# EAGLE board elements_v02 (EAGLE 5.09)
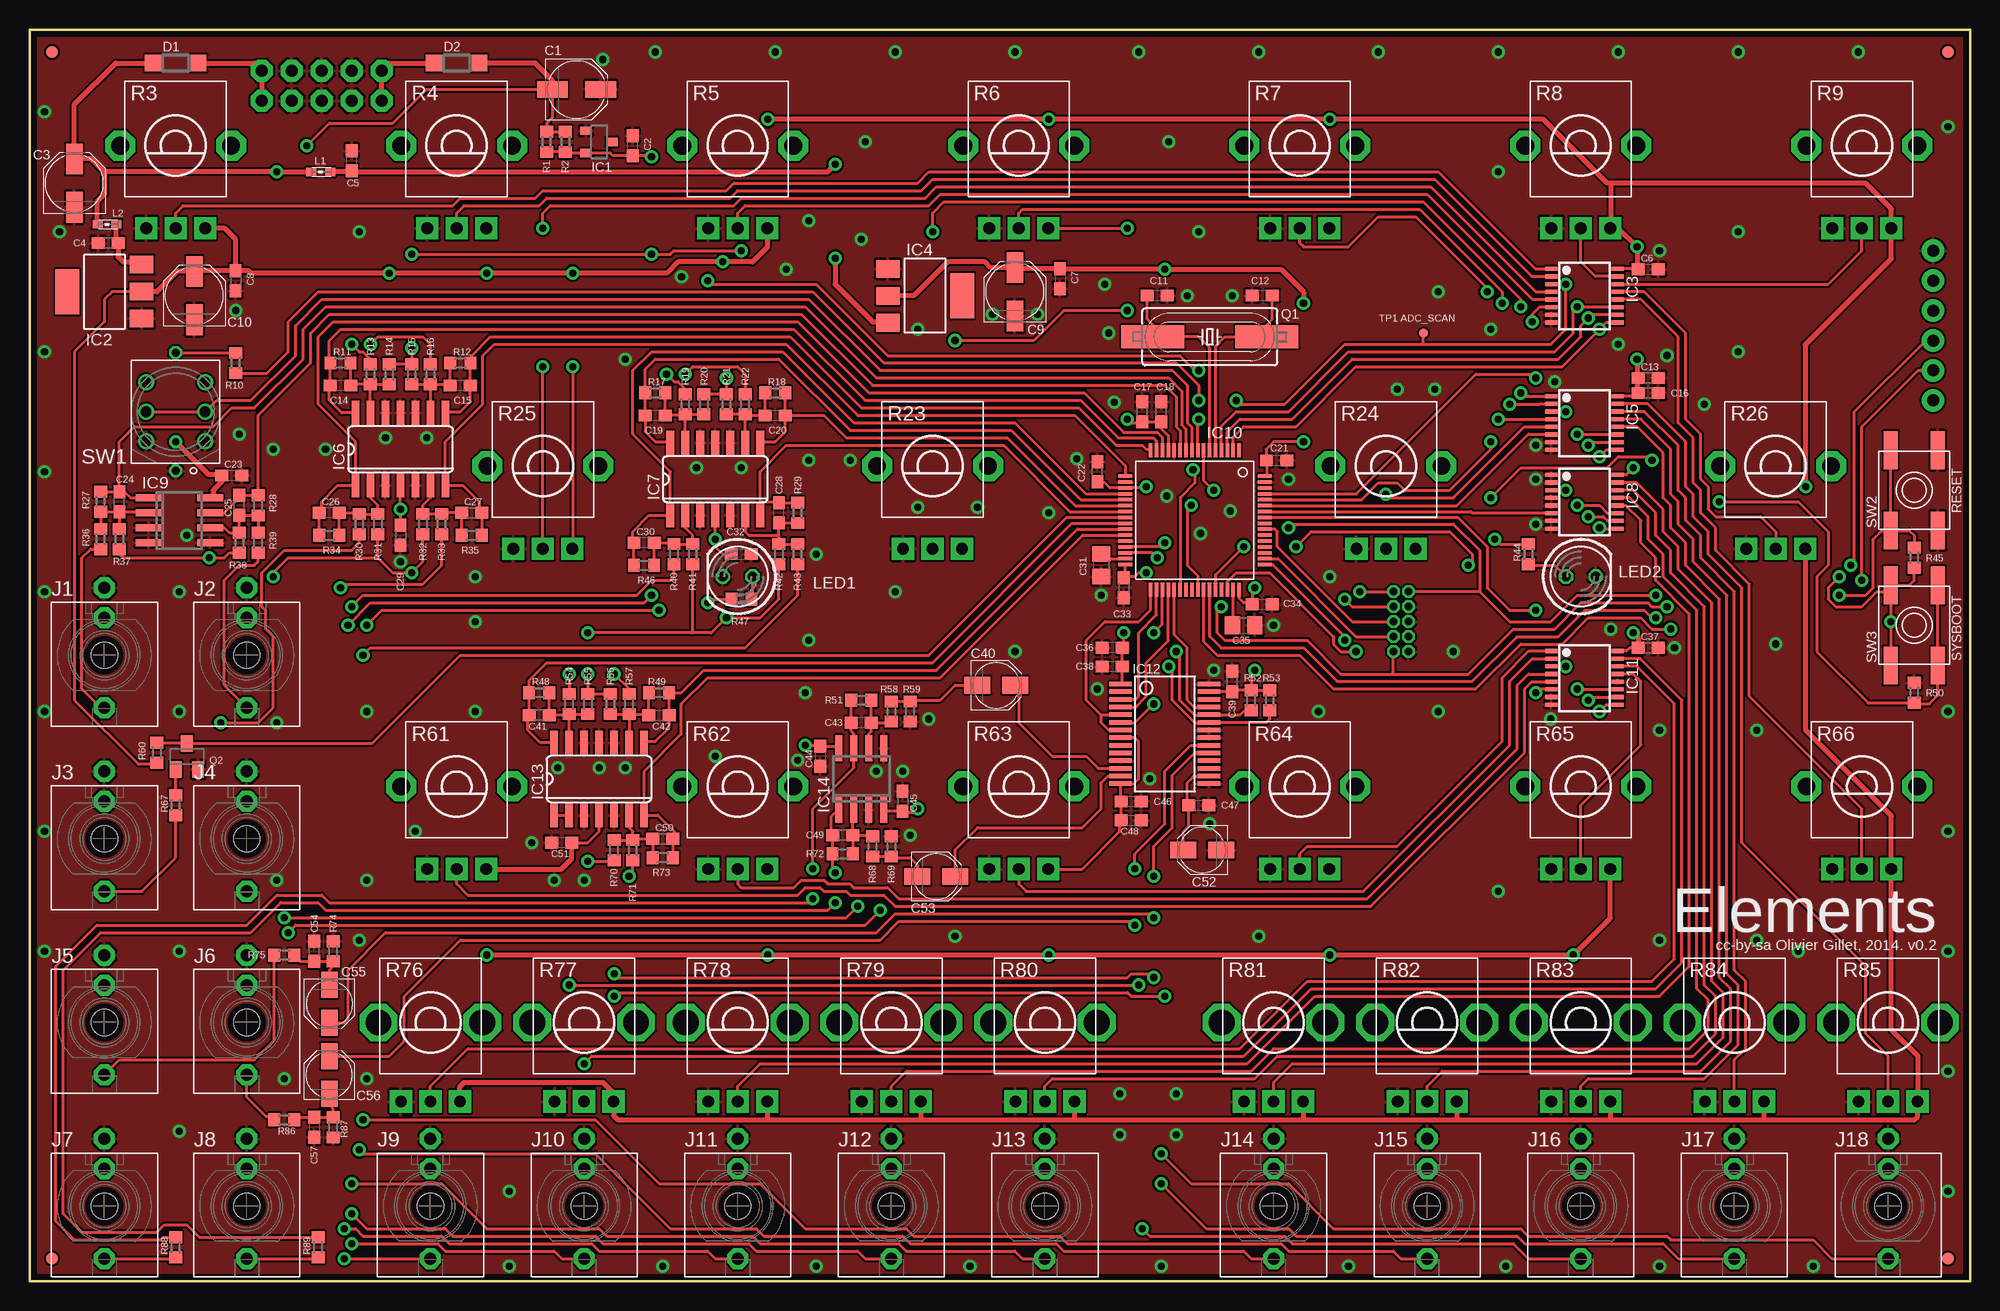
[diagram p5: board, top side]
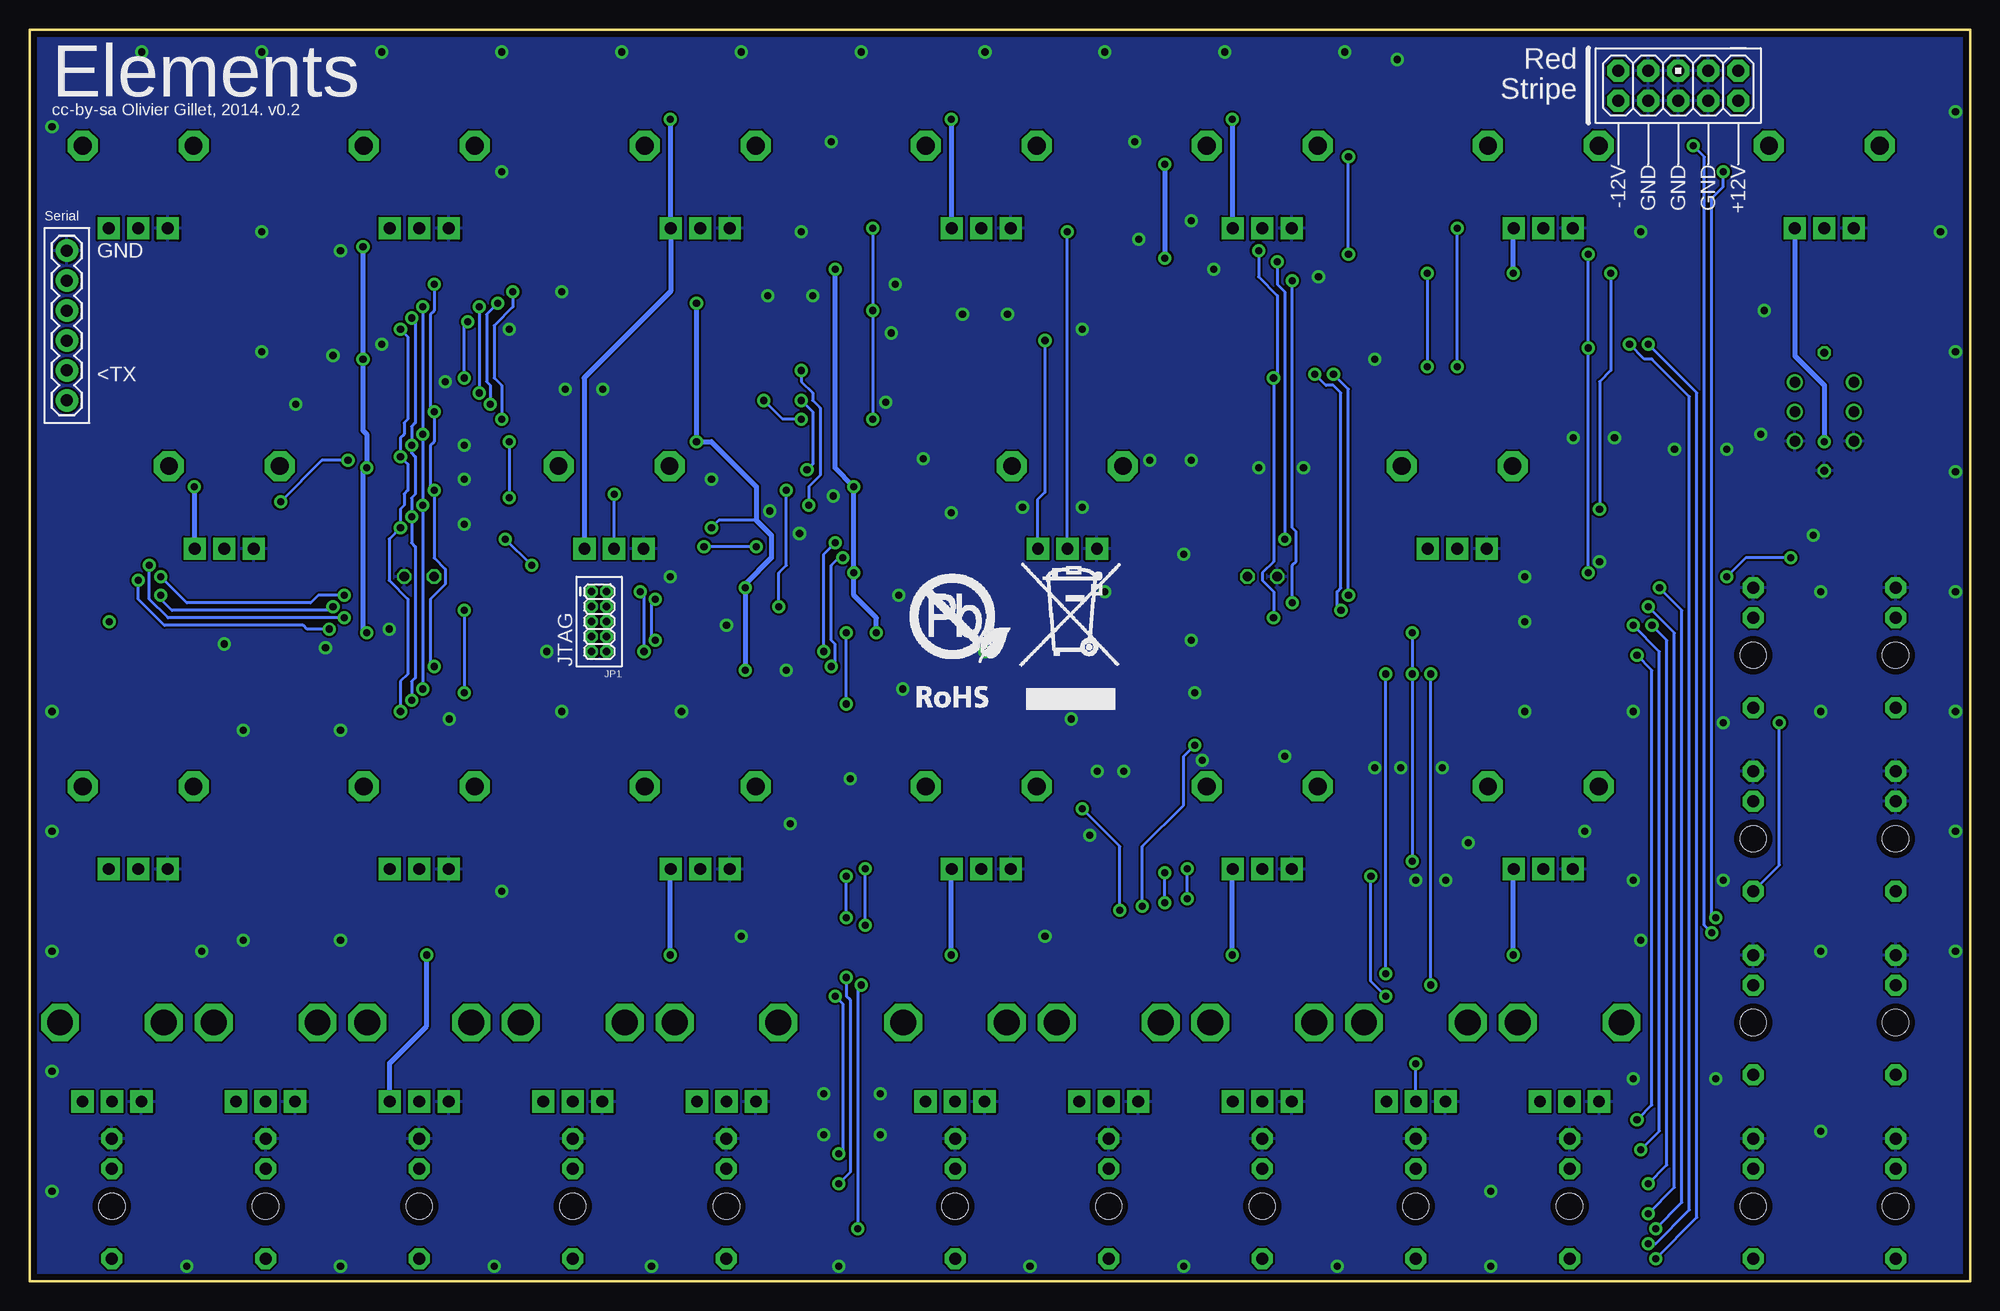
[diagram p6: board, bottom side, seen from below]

Size 164.47 x 106.05 mm. Coordinates in mm from the lower left corner, seen from the top.
Outline: 0,0 164.47,0 164.47,106.05 0,106.05 0,0
Copper layers (1*16): Top 0.035mm / dielectric 1.5mm / Bottom 0.035mm
Design rules "PCBCart-Standard-Fine": minimum track width 8mil, minimum drill 0.4mm, track to track 7mil, track to pad 7mil, pad to pad 7mil, via to via 7mil, smd to smd 7mil, copper to edge 20mil, drill to drill 8mil, minimum pad ring 8mil, minimum via ring 10mil, stop-mask expansion 3mil, vias tented up to drill 25mil, thermal gap 8mil

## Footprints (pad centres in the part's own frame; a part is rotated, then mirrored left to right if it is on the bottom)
PANASONIC_C = smd 2.6 x 1.4: + 2.05,0; - -2.05,0
C0603 = smd 1.1 x 1: 1 -0.85,0; 2 0.85,0
C0805 = smd 1.3 x 1.5: 1 -0.95,0; 2 0.95,0
PANASONIC_B = smd 2.2 x 1.4: + 1.6,0; - -1.6,0
SOD123 = smd 1.4 x 1.4: A 1.9,0; C -1.9,0
FIDUCIAL-1X2 = smd 1 x 1: 1 0,0
DBZ_R-PDSO-G3 = smd 0.7 x 1: 1 -0.95,-1.1; 2 0.95,-1.1; 3 0,1.1
SOT223 = smd 1.499 x 2.007: 1 -2.261,-3.15; 2 0.025,-3.15; 3 2.311,-3.15 | smd 3.81 x 2.007: 4 0,3.15
TSSOP16 = smd 0.35 x 1: 1 -1.95,-2.825; 2 -1.3,-2.825; 3 -0.65,-2.825; 4 0,-2.825; 5 0.65,-2.825; 6 1.3,-2.825; 7 1.95,-2.825; 8 2.6,-2.825; 9 2.6,2.825; 10 1.95,2.825; 11 1.3,2.825; 12 0.65,2.825; 13 0,2.825; 14 -0.65,2.825; 15 -1.3,2.825; 16 -1.95,2.825
SO14 = smd 0.66 x 2.032: 1 -3.81,-3.073; 2 -2.54,-3.073; 3 -1.27,-3.073; 4 0,-3.073; 5 1.27,-3.073; 6 2.54,-3.073; 7 3.81,-3.073; 8 3.81,3.073; 9 2.54,3.073; 10 1.27,3.073; 11 0,3.073; 12 -1.27,3.073; 13 -2.54,3.073; 14 -3.81,3.073
SO08 = smd 0.6 x 2.2: 1 -1.905,-2.6; 2 -0.635,-2.6; 3 0.635,-2.6; 4 1.905,-2.6; 5 1.905,2.6; 6 0.635,2.6; 7 -0.635,2.6; 8 -1.905,2.6
TQFP-10X10-64 = smd 1.2 x 0.3: 1 -5.936,3.75; 2 -5.936,3.25; 3 -5.936,2.75; 4 -5.936,2.25; 5 -5.936,1.75; 6 -5.936,1.25; 7 -5.936,0.75; 8 -5.936,0.25; 9 -5.936,-0.25; 10 -5.936,-0.75; 11 -5.936,-1.25; 12 -5.936,-1.75; 13 -5.936,-2.25; 14 -5.936,-2.75; 15 -5.936,-3.25; 16 -5.936,-3.75; 33 5.886,-3.75; 34 5.886,-3.25; 35 5.886,-2.75; 36 5.886,-2.25; 37 5.886,-1.75; 38 5.886,-1.25; 39 5.886,-0.75; 40 5.886,-0.25; 41 5.886,0.25; 42 5.886,0.75; 43 5.886,1.25; 44 5.886,1.75; 45 5.886,2.25; 46 5.886,2.75; 47 5.886,3.25; 48 5.886,3.75 | smd 0.3 x 1.2: 17 -3.75,-5.911; 18 -3.25,-5.911; 19 -2.75,-5.911; 20 -2.25,-5.911; 21 -1.75,-5.911; 22 -1.25,-5.911; 23 -0.75,-5.911; 24 -0.25,-5.911; 25 0.25,-5.911; 26 0.75,-5.911; 27 1.25,-5.911; 28 1.75,-5.911; 29 2.25,-5.911; 30 2.75,-5.911; 31 3.25,-5.911; 32 3.75,-5.911; 49 3.75,5.936; 50 3.25,5.936; 51 2.75,5.936; 52 2.25,5.936; 53 1.75,5.936; 54 1.25,5.936; 55 0.75,5.936; 56 0.25,5.936; 57 -0.25,5.936; 58 -0.75,5.936; 59 -1.25,5.936; 60 -1.75,5.936; 61 -2.25,5.936; 62 -2.75,5.936; 63 -3.25,5.936; 64 -3.75,5.936
SSOP28 = smd 0.381 x 1.905: 1 -4.55,-3.752; 2 -3.9,-3.752; 3 -3.25,-3.752; 4 -2.6,-3.752; 5 -1.95,-3.752; 6 -1.3,-3.752; 7 -0.65,-3.752; 8 0,-3.752; 9 0.65,-3.752; 10 1.3,-3.752; 11 1.95,-3.752; 12 2.6,-3.752; 13 3.25,-3.752; 14 3.9,-3.752; 15 3.9,3.752; 16 3.25,3.752; 17 2.6,3.752; 18 1.95,3.752; 19 1.3,3.752; 20 0.65,3.752; 21 0,3.752; 22 -0.65,3.752; 23 -1.3,3.752; 24 -1.95,3.752; 25 -2.6,3.752; 26 -3.25,3.752; 27 -3.9,3.752; 28 -4.55,3.752
WQP_PJ_301M6 = drill 1.016 pad 1.778 octagon: P1 0,-5.715; P2 0,-3.175; P3 0,4.445 | hole 2.2: 0,0
2X5-1.27 = drill 0.61 pad 1.067 octagon: 1 -1.27,3.81; 2 0,3.81; 3 -1.27,2.54; 4 0,2.54; 5 -1.27,1.27; 6 0,1.27; 7 -1.27,0; 8 0,0; 9 -1.27,-1.27; 10 0,-1.27
1X06 = drill 1.016 pad 1.88 round: 1 0,0; 2 2.54,0; 3 5.08,0; 4 7.62,0; 5 10.16,0; 6 12.7,0
AVR_ICSP = drill 1.016 pad 1.88 octagon: 1 -1.27,5.08; 2 1.27,5.08; 3 -1.27,2.54; 4 1.27,2.54; 5 -1.27,0; 6 1.27,0; 7 -1.27,-2.54; 8 1.27,-2.54; 9 -1.27,-5.08; 10 1.27,-5.08
0603 = smd 0.85 x 0.7: 1 -0.9,0; 2 0.7,0
LED5MM = drill 0.813 octagon: A -1.27,0; K 1.27,0
HC49UP = smd 5.334 x 1.93: 1 -4.826,0; 2 4.826,0
SOT23-BEC = smd 1 x 1.4: B -0.95,-1.1; C 0,1.1; E 0.95,-1.1
R0603 = smd 1 x 1.1: 1 -0.85,0; 2 0.85,0
ALPS_POT_VERTICAL_PS = drill 1 pad 1.88 square: P$1 -2.5,7; P$2 0,7; P$3 2.5,7 | drill 1.5 pad 2.54 octagon: P$4 -4.7,0; P$5 4.7,0
ALPS_POT_VERTICAL = drill 1 pad 1.88 square: P$1 -2.5,6.7; P$2 0,6.7; P$3 2.5,6.7 | drill 2.2 pad 3.175 octagon: P$4 -4.4,0; P$5 4.4,0
LP4OA1PBCT = drill 0.7 octagon: L1 5,0; L2 -5,0 | drill 0.9 round: P1 2.5,2.5; P2 0,2.5; P3 -2.5,2.5; P4 2.5,-2.5; P5 0,-2.5; P6 -2.5,-2.5
EVQ-Q2 = smd 3.2 x 1.2: A -3.4,-2; A' 3.4,-2; B -3.4,2; B' 3.4,2
PAD.03X.03 = smd 0.762 x 0.762: P$1 0,0

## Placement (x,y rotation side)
C1  22u  [PANASONIC_C]  46.35,100.97 0 top
C2  100n  [C0603]  51.12,96.2 90 top
C3  22u  [PANASONIC_C]  3.81,93.03 90 top
C4  100n  [C0603]  6.67,87.95 180 top
C5  100n  [C0603]  27.3,94.93 90 top
C6  100n  [C0603]  137.16,85.72 0 top
C7  100n  [C0603]  87.31,84.93 270 top
C8  100n  [C0603]  17.46,84.77 270 top
C9  22u  [PANASONIC_C]  83.5,83.82 90 top
C10  22u  [PANASONIC_C]  13.97,83.5 90 top
C11  18p  [C0603]  95.57,83.5 180 top
C12  18p  [C0603]  104.46,83.5 0 top
C13  100n  [C0603]  137.16,76.52 0 top
C14  3.3n  [C0603]  26.35,75.88 180 top
C15  3.3n  [C0603]  36.51,75.88 0 top
C16  100n  [C0603]  137.16,75.25 0 top
C17  1u  [C0603]  94.3,73.66 90 top
C18  100n  [C0603]  95.89,73.66 90 top
C19  3.3n  [C0603]  53.02,73.34 180 top
C20  3.3n  [C0603]  63.18,73.34 0 top
C21  100n  [C0603]  105.66,69.53 0 top
C22  100n  [C0603]  90.49,68.58 90 top
C23  100n  [C0603]  17.14,68.26 0 top
C24  3.3n  [C0603]  7.62,66.04 90 top
C25  3.3n  [C0603]  17.78,65.72 90 top
C26  3.3n  [C0603]  25.4,65.09 180 top
C27  3.3n  [C0603]  37.47,65.09 0 top
C28  3.3n  [C0603]  63.5,65.09 90 top
C29  100n  [C0603]  31.43,63.18 270 top
C30  3.3n  [C0603]  52.07,62.55 180 top
C31  2.2u  [C0805]  90.81,60.64 270 top
C32  100n  [C0603]  60.33,61.59 0 top
C33  100n  [C0603]  92.71,58.74 270 top
C34  100n  [C0603]  104.46,57.34 0 top
C35  2.2u  [C0805]  102.87,55.56 0 top
C36  1u  [C0603]  91.76,53.66 180 top
C37  100n  [C0603]  137.16,53.66 0 top
C38  100n  [C0603]  91.76,52.07 180 top
C39  100n  [C0603]  101.92,50.8 90 top
C40  10u  [PANASONIC_B]  81.92,50.48 0 top
C41  3.3n  [C0603]  43.18,47.94 180 top
C42  3.3n  [C0603]  53.34,47.94 0 top
C43  18p  [C0603]  70.48,47.31 180 top
C44  100n  [C0603]  66.99,44.45 270 top
C45  100n  [C0603]  73.98,40.64 270 top
C46  100n  [C0603]  93.34,40.64 0 top
C47  100n  [C0603]  99.06,40.32 0 top
C48  1u  [C0603]  93.34,39.05 0 top
C49  18p  [C0603]  68.9,37.78 180 top
C50  3.3n  [C0603]  53.66,37.47 0 top
C51  100n  [C0603]  45.09,37.15 180 top
C52  10u  [PANASONIC_B]  99.38,36.51 180 top
C53  10u  [PANASONIC_B]  76.83,34.29 0 top
C54  220p  [C0603]  24.13,27.94 90 top
C55  10u  [PANASONIC_B]  25.4,23.5 270 top
C56  10u  [PANASONIC_B]  25.4,17.46 90 top
C57  220p  [C0603]  24.13,13.02 270 top
D1  1N5819HW  [SOD123]  12.38,103.19 0 top
D2  1N5819HW  [SOD123]  36.2,103.19 0 top
F1  FIDUCIAL1X2  [FIDUCIAL-1X2]  1.91,104.14 0 top
F2  FIDUCIAL1X2  [FIDUCIAL-1X2]  162.56,104.14 0 top
F3  FIDUCIAL1X2  [FIDUCIAL-1X2]  1.91,1.91 0 top
F4  FIDUCIAL1X2  [FIDUCIAL-1X2]  162.56,1.91 0 top
IC1  LM4040B10  [DBZ_R-PDSO-G3]  48.26,96.52 270 top
IC2  LM1117-3.3  [SOT223]  6.35,83.82 90 top
IC3  4051PW  [TSSOP16]  131.76,83.82 270 top
IC4  LM1117-3.3  [SOT223]  75.88,83.5 270 top
IC5  4051PW  [TSSOP16]  131.76,73.03 270 top
IC6  MCP6004  [SO14]  31.43,70.48 0 top
IC7  MCP6004  [SO14]  58.1,67.94 0 top
IC8  4051PW  [TSSOP16]  131.76,66.36 270 top
IC9  MCP6002  [SO08]  12.7,64.45 270 top
IC10  STM32F405RGT6  [TQFP-10X10-64]  98.74,64.45 270 top
IC11  4051PW  [TSSOP16]  131.76,51.44 270 top
IC12  WM8731  [SSOP28]  96.2,46.04 270 top
IC13  MCP6004  [SO14]  48.26,42.55 0 top
IC14  LME49720  [SO08]  70.48,42.55 0 top
J1  PJ301_THONKICONN6  [WQP_PJ_301M6]  6.35,53.02 180 top
J2  PJ301_THONKICONN6  [WQP_PJ_301M6]  18.41,53.02 180 top
J3  PJ301_THONKICONN6  [WQP_PJ_301M6]  6.35,37.47 180 top
J4  PJ301_THONKICONN6  [WQP_PJ_301M6]  18.41,37.47 180 top
J5  PJ301_THONKICONN6  [WQP_PJ_301M6]  6.35,21.91 180 top
J6  PJ301_THONKICONN6  [WQP_PJ_301M6]  18.41,21.91 180 top
J7  PJ301_THONKICONN6  [WQP_PJ_301M6]  6.35,6.35 180 top
J8  PJ301_THONKICONN6  [WQP_PJ_301M6]  18.41,6.35 180 top
J9  PJ301_THONKICONN6  [WQP_PJ_301M6]  33.97,6.35 180 top
J10  PJ301_THONKICONN6  [WQP_PJ_301M6]  46.99,6.35 180 top
J11  PJ301_THONKICONN6  [WQP_PJ_301M6]  60.01,6.35 180 top
J12  PJ301_THONKICONN6  [WQP_PJ_301M6]  73.03,6.35 180 top
J13  PJ301_THONKICONN6  [WQP_PJ_301M6]  86.04,6.35 180 top
J14  PJ301_THONKICONN6  [WQP_PJ_301M6]  105.41,6.35 180 top
J15  PJ301_THONKICONN6  [WQP_PJ_301M6]  118.43,6.35 180 top
J16  PJ301_THONKICONN6  [WQP_PJ_301M6]  131.44,6.35 180 top
J17  PJ301_THONKICONN6  [WQP_PJ_301M6]  144.46,6.35 180 top
J18  PJ301_THONKICONN6  [WQP_PJ_301M6]  157.48,6.35 180 top
JP1  M05X2MINIJTAG  [2X5-1.27]  115.57,54.61 0 bottom
JP2  [1X06]  161.29,87.31 270 bottom
JP3  M05X2PTH  [AVR_ICSP]  24.77,101.28 270 bottom
L1  [0603]  24.77,93.98 0 top
L2  [0603]  6.67,89.53 0 top
LED1  SSL-LX5093TC  [LED5MM]  60.01,59.69 180 top
LED2  SSL-LX5093PC  [LED5MM]  131.44,59.69 0 top
Q1  8MHz  [HC49UP]  100.01,80.01 0 top
Q2  MMBT3904  [SOT23-BEC]  13.34,44.45 0 top
R1  1.0k  [R0603]  43.81,96.52 270 top
R2  1.0k  [R0603]  45.4,96.52 270 top
R3  10kB  [ALPS_POT_VERTICAL_PS]  12.38,96.2 180 top
R4  10kB  [ALPS_POT_VERTICAL_PS]  36.2,96.2 180 top
R5  10kB  [ALPS_POT_VERTICAL_PS]  60.01,96.2 180 top
R6  10kB  [ALPS_POT_VERTICAL_PS]  83.82,96.2 180 top
R7  10kB  [ALPS_POT_VERTICAL_PS]  107.63,96.2 180 top
R8  10kB  [ALPS_POT_VERTICAL_PS]  131.44,96.2 180 top
R9  10kB  [ALPS_POT_VERTICAL_PS]  155.26,96.2 180 top
R10  33  [R0603]  17.46,77.79 90 top
R11  20k  [R0603]  26.35,77.79 0 top
R12  20k  [R0603]  36.51,77.79 180 top
R13  100k  [R0603]  28.89,76.83 90 top
R14  120k  [R0603]  30.48,76.83 90 top
R15  120k  [R0603]  32.38,76.83 90 top
R16  100k  [R0603]  33.97,76.83 90 top
R17  20k  [R0603]  53.02,75.25 0 top
R18  20k  [R0603]  63.18,75.25 180 top
R19  100k  [R0603]  55.56,74.3 90 top
R20  120k  [R0603]  57.15,74.3 90 top
R21  120k  [R0603]  59.05,74.3 90 top
R22  100k  [R0603]  60.64,74.3 90 top
R23  10kB  [ALPS_POT_VERTICAL_PS]  76.52,69.06 180 top
R24  10kB  [ALPS_POT_VERTICAL_PS]  114.94,69.06 180 top
R25  10kB  [ALPS_POT_VERTICAL_PS]  43.5,69.06 180 top
R26  10kB  [ALPS_POT_VERTICAL_PS]  147.96,69.06 180 top
R27  47k  [R0603]  6.03,66.04 270 top
R28  20k  [R0603]  19.37,65.72 270 top
R29  20k  [R0603]  65.09,65.09 270 top
R30  100k  [R0603]  27.94,64.14 270 top
R31  200k  [R0603]  29.53,64.14 270 top
R32  120k  [R0603]  33.34,64.14 270 top
R33  100k  [R0603]  34.92,64.14 270 top
R34  33k  [R0603]  25.4,63.18 0 top
R35  20k  [R0603]  37.47,63.18 180 top
R36  100k  [R0603]  6.03,62.87 270 top
R37  180k  [R0603]  7.62,62.87 270 top
R38  120k  [R0603]  17.78,62.55 270 top
R39  100k  [R0603]  19.37,62.55 270 top
R40  100k  [R0603]  54.61,61.59 270 top
R41  120k  [R0603]  56.2,61.59 270 top
R42  120k  [R0603]  63.5,61.59 270 top
R43  100k  [R0603]  65.09,61.59 270 top
R44  2.2k  [R0603]  127,61.59 270 top
R45  10k  [R0603]  159.7,61.28 270 top
R46  20k  [R0603]  52.07,60.64 0 top
R47  2.2k  [R0603]  60.33,57.78 0 top
R48  20k  [R0603]  43.18,49.85 0 top
R49  20k  [R0603]  53.34,49.85 180 top
R50  10k  [R0603]  159.7,49.85 270 top
R51  47k  [R0603]  70.48,49.21 0 top
R52  2.2k  [R0603]  103.5,49.21 90 top
R53  2.2k  [R0603]  105.09,49.21 90 top
R54  100k  [R0603]  45.72,48.9 90 top
R55  120k  [R0603]  47.31,48.9 90 top
R56  120k  [R0603]  49.21,48.9 90 top
R57  100k  [R0603]  50.8,48.9 90 top
R58  6.8k  [R0603]  73.03,48.26 90 top
R59  47k  [R0603]  74.61,48.26 90 top
R60  10k  [R0603]  10.79,44.77 270 top
R61  10kB  [ALPS_POT_VERTICAL_PS]  36.2,41.91 180 top
R62  10kB  [ALPS_POT_VERTICAL_PS]  60.01,41.91 180 top
R63  10kB  [ALPS_POT_VERTICAL_PS]  83.82,41.91 180 top
R64  10kB  [ALPS_POT_VERTICAL_PS]  107.63,41.91 180 top
R65  10kB  [ALPS_POT_VERTICAL_PS]  131.44,41.91 180 top
R66  10kB  [ALPS_POT_VERTICAL_PS]  155.26,41.91 180 top
R67  100k  [R0603]  12.38,40.32 90 top
R68  6.8k  [R0603]  71.44,36.83 270 top
R69  47k  [R0603]  73.03,36.83 270 top
R70  120k  [R0603]  49.53,36.51 270 top
R71  100k  [R0603]  51.12,36.51 270 top
R72  47k  [R0603]  68.9,36.2 0 top
R73  20k  [R0603]  53.66,35.88 180 top
R74  6.8k  [R0603]  25.72,27.94 270 top
R75  36k  [R0603]  21.59,27.62 180 top
R76  10kB  [ALPS_POT_VERTICAL]  33.97,21.91 180 top
R77  10kB  [ALPS_POT_VERTICAL]  46.99,21.91 180 top
R78  10kB  [ALPS_POT_VERTICAL]  60.01,21.91 180 top
R79  10kB  [ALPS_POT_VERTICAL]  73.03,21.91 180 top
R80  10kB  [ALPS_POT_VERTICAL]  86.04,21.91 180 top
R81  10kB  [ALPS_POT_VERTICAL]  105.41,21.91 180 top
R82  10kB  [ALPS_POT_VERTICAL]  118.43,21.91 180 top
R83  10kB  [ALPS_POT_VERTICAL]  131.44,21.91 180 top
R84  10kB  [ALPS_POT_VERTICAL]  144.46,21.91 180 top
R85  10kB  [ALPS_POT_VERTICAL]  157.48,21.91 180 top
R86  36k  [R0603]  21.59,13.65 180 top
R87  6.8k  [R0603]  25.72,13.02 90 top
R88  1.0k  [R0603]  12.38,2.86 90 top
R89  1.0k  [R0603]  24.45,2.86 90 top
SW1  LP4OA1PBCT  [LP4OA1PBCT]  12.38,73.66 90 top
SW2  [EVQ-Q2]  159.7,66.99 90 top
SW3  [EVQ-Q2]  159.7,55.56 90 top
TP1  ADC_TEST  [PAD.03X.03]  118.11,80.33 0 top
U$2  [ROHS_BIG]  91.12,47.62 0 bottom

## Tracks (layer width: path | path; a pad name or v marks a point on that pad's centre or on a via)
+3V3  (via drill 0.6)
  Top 0.254: R45.2 159.7,59.37 159.29,58.96 SW3.B' | R52.2 R53.2 | R52.2 102.03,50.06 C39.1 101.91,49.94 IC12.27 | IC10.48 102.49,57.84 102.87,57.47 103.48,57.47 C34.1 103.61,58.52 v103.82,58.74 | 122.87,58.42 JP1.1 | 122.87,58.42 125.41,55.88 128.91,55.88 131.13,58.1 v137.79,58.1 | R52.2 103.5,51.44 v103.82,51.75 | IC10.64 104.81,68.34 C21.1 104.78,69.57 104.78,70.48 105.41,71.12 v107.95,71.12 | IC12.1 92.61,50.74 C38.1 C36.1 92.71,53.76 v92.71,54.93 | 92.81,59.69 C33.1 | 92.81,59.69 93.66,59.69 93.98,60.01 v94.61,60.01 | 92.81,59.69 92.83,59.71 IC10.32 | v94.61,67.31 94.51,67.2 IC10.19 91.55,67.2 91.12,67.63 90.59,67.63 C22.1 | SW3.B' v157.7,55.88 SW3.B | v106.68,63.82 107,64.14 120.65,64.14 122.87,61.91 122.87,58.42 | SW3.B' 157.16,58.42 156.53,58.42 155.26,57.15 153.03,57.15 152.4,57.78 152.4,58.74 v153.35,59.69
  Top 0.406: IC4.2 72.76,83.5 74.93,83.5 77.79,86.36 80.96,86.36 81.45,85.87 C9.+ 83.59,85.78 C7.1 87.37,85.72 v96.2,85.72 106.05,85.72 107.95,83.82 v107.95,82.87
  Bottom 0.254: v153.35,59.69 151.13,57.47 140.65,57.47 140.02,58.1 v137.79,58.1 | v106.68,63.82 106.05,64.45 102.87,64.45
  Bottom 0.406: v107.95,82.87 v107.95,71.12 106.68,71.12 102.87,67.31 102.87,64.45 101.6,63.18 101.6,61.28 103.82,59.05 v103.82,58.74 v103.82,51.75 | v92.71,54.93 92.71,56.2 94.61,58.1 v94.61,60.01 v94.61,67.31 96.2,68.9 v96.2,85.72
+3V3_A  (via drill 0.6)
  Top 0.254: C37.1 136.26,53.7 136.22,53.66 135.57,53.66 135.3,53.38 IC11.16 | 136.21,85.83 136.15,85.77 IC3.16 | IC5.16 135.83,74.97 136.21,75.35 136.31,75.45 C13.1 | IC12.8 93.66,46.04 93.98,45.72 93.98,42.55 93.57,42.14 IC12.14 92.45,40.69 C46.1 C48.1 92.39,38.95 92.39,38.1 89.2,34.91 R63.P$1 | C18.1 95.89,72.23 96.49,71.62 IC10.13 | C18.1 | C18.1 C17.1 94.19,72.71 93.34,72.71 v93.03,73.03 | v93.03,89.22 93.01,89.2 R6.P$1 | C29.1 v31.43,65.41 IC6.4 | C51.1 47.31,37.15 48.26,38.1 IC13.4 | R60.2 10.69,43.81 9.21,43.81 3.81,49.21 3.81,78.74 6.35,81.28 6.35,83.19 7.01,83.84 IC2.2 | R25.P$1 46.04,62.1 v46.04,77.47 | IC7.4 v58.1,62.87 58.1,62.23 58.74,61.59 C32.1 | v78.42,79.69 85.09,79.69 87.63,82.23 v93.03,82.23 | v135.89,68.9 135.3,68.31 IC8.16
  Top 0.406: 88.58,13.65 107.95,13.65 | 107.95,13.65 120.97,13.65 | 120.97,13.65 133.99,13.65 | 133.99,13.65 147,13.65 | 147,13.65 159.7,13.65 159.98,13.93 R85.P$1 160.02,15.25 160.02,19.05 157.76,21.31 R66.P$1 157.76,39.41 150.5,46.67 150.5,62.02 R26.P$1 | R84.P$1 147,15.17 147,13.65 | R83.P$1 133.99,15.17 133.99,13.65 | R82.P$1 120.97,15.17 120.97,13.65 | R81.P$1 107.95,15.17 107.95,13.65 | R80.P$1 88.58,15.17 88.58,13.65 | v62.55,98.42 v86.36,98.42 v110.17,98.42 128.27,98.42 133.67,93.03 133.99,93.03 | C8.1 14.04,85.62 C10.+ 12.53,85.55 10.79,83.82 9.53,83.82 IC2.2 | C6.1 136.21,85.83 v136.21,87.63 134.63,89.2 R8.P$1 133.99,89.24 133.99,93.03 | C16.1 136.21,75.35 v136.21,78.11 | v38.73,27.62 v62.55,27.62 v86.36,27.62 v110.17,27.62 v130.81,27.62 133.94,30.76 R65.P$1 | 133.99,93.03 155.57,93.03 157.76,90.84 R9.P$1 157.76,86.64 150.46,79.33 150.5,79.3 v150.5,67.31 | R76.P$1 36.47,16.47 36.83,16.83 48.58,16.83 49.49,15.91 R77.P$1 49.49,14.01 49.85,13.65 62.55,13.65 | 62.55,15.25 R78.P$1 62.55,15.17 62.55,13.65 | 75.56,13.65 88.58,13.65 | R79.P$1 75.56,15.17 75.56,13.65 | C51.1 45.94,35.77 45.07,34.91 R61.P$1 | R5.P$1 62.51,87.59 61.28,86.36 v58.74,86.36 54.93,86.36 53.98,85.41 v46.04,85.41 v38.73,85.41 v30.48,85.41 18.73,85.41 18.52,85.62 C8.1 | v12.38,71.12 15.14,68.36 16.3,68.36 C23.1 16.3,67.73 15.56,66.99 15.56,66.61 IC9.8 | C8.1 17.46,88.27 16.52,89.2 R3.P$1 | 62.55,13.65 75.56,13.65 | v135.89,54.93 136.31,54.51 C37.1
  Bottom 0.254: v93.03,89.22 v93.03,82.23 v93.03,73.03 | v31.43,65.41 31.43,76.2 30.48,77.15 v30.48,85.41 | v46.04,85.41 v46.04,77.47 | v58.74,86.36 58.74,84.45 58.1,83.82 v58.1,62.87 | R23.P$1 79.06,62.1 79.06,66.2 78.42,66.83 v78.42,79.69
  Bottom 0.406: R5.P$1 62.55,89.24 v62.55,98.42 | R6.P$1 86.36,89.24 v86.36,98.42 | v110.17,98.42 110.17,89.24 R7.P$1 110.13,83.86 117.47,76.52 117.47,62.1 R24.P$1 | v135.89,54.93 136.21,55.24 136.21,68.58 v135.89,68.9 135.89,71.75 136.21,72.07 v136.21,78.11 v136.21,87.63 | R9.P$1 157.8,89.24 | R83.P$1 133.94,18.45 130.81,21.59 v130.81,27.62 | R61.P$1 38.73,34.87 v38.73,27.62 | R62.P$1 62.55,34.87 v62.55,27.62 | R63.P$1 86.36,34.87 v86.36,27.62 | R64.P$1 110.17,34.87 v110.17,27.62 | v150.5,67.31 150.46,67.27 R26.P$1 | v12.38,71.12 12.38,75.88 14.88,78.38 R3.P$1 | R4.P$1 38.73,89.16 v38.73,85.41
ADC_ADDR_0  (via drill 0.6)
  Top 0.254: IC3.11 134.56,82.55 v131.13,82.55 130.81,82.23 130.81,80.33 129.22,78.74 111.76,78.74 106.68,73.66 102.23,73.66 100.99,72.42 IC10.4 100.97,70.42 | v131.13,50.16 131.16,50.13 IC11.11 | IC5.11 134.56,71.75 v131.13,71.75 | 134.56,65.09 IC8.11 133.7,65.06 133.03,65.72 v131.13,65.72
  Bottom 0.254: v131.13,50.16 v131.13,65.72 v131.13,71.75 v131.13,82.55
ADC_ADDR_1  (via drill 0.6)
  Top 0.254: IC3.10 134.54,81.92 132.4,81.92 v132.08,81.6 131.44,80.96 131.44,80.01 129.54,78.11 112.08,78.11 107,73.03 102.55,73.03 101.49,71.97 IC10.3 | v132.08,49.21 132.35,49.48 IC11.10 | v132.08,70.8 132.35,71.08 IC5.10 | v132.08,64.77 133.35,64.77 133.71,64.41 IC8.10
  Bottom 0.254: v132.08,49.21 132.08,50.8 131.76,51.12 131.76,62.23 132.08,62.55 v132.08,64.77 132.08,66.36 131.76,66.67 131.76,69.85 132.08,70.17 v132.08,70.8 132.08,72.39 131.76,72.71 131.76,81.28 v132.08,81.6
ADC_ADDR_2  (via drill 0.6)
  Top 0.254: IC3.9 133.61,81.22 v133.03,80.64 129.86,77.47 112.39,77.47 107.31,72.39 102.87,72.39 101.99,71.51 IC10.2 | v133.03,69.85 133.61,70.42 IC5.9 | v133.03,48.26 133.61,48.84 IC11.9 | v133.03,63.82 133.09,63.76 IC8.9
  Bottom 0.254: v133.03,80.64 132.4,80.01 132.4,73.03 132.72,72.71 132.72,71.75 133.03,71.44 v133.03,69.85 132.4,69.22 132.4,66.99 132.72,66.67 132.72,65.72 133.03,65.41 v133.03,63.82 133.99,62.87 133.99,59.37 132.4,57.78 132.4,51.44 133.03,50.8 v133.03,48.26
ADC_BANK_0  (via drill 0.6)
  Top 0.254: IC11.6 128.91,50.16 127.95,50.16 v127.64,49.85 | IC10.57 121.03,64.7 123.51,62.23 123.51,58.74 125.41,56.83 v127.64,56.83
  Bottom 0.254: v127.64,56.83 v127.64,49.85
ADC_BANK_1
  Top 0.254: IC8.6 128.91,65.09 122.24,65.09 122.12,65.2 IC10.58
ADC_BANK_2
  Top 0.254: IC5.6 128.91,71.75 127,71.75 120.95,65.7 IC10.59
ADC_BANK_3  (via drill 0.6)
  Top 0.254: IC3.6 128.91,82.55 127.95,82.55 127.32,81.92 v127.32,81.28 | v127.64,76.52 127.32,76.83 122.56,76.83 112.42,66.7 IC10.61
  Bottom 0.254: v127.32,81.28 127.64,80.96 v127.64,76.52
ADC_BLOW_SHAPE
  Top 0.254: IC10.16 94.9,70.48 94.61,70.48 94.3,70.8 92.08,70.8 88.9,73.98 70.48,73.98 64.45,80.01 39.05,80.01 37.47,78.42 37.47,77.89 R12.1 C15.2 37.36,74.51 36.51,73.66 35.34,73.66 IC6.8
ADC_BLOW_TIMBRE
  Top 0.254: IC10.17 92.83,69.09 88.58,73.34 70.17,73.34 64.14,79.38 39.37,79.38 38.42,78.42 38.42,74.3 35.24,71.12 IC6.7 36.73,67.41 38.1,66.04 38.1,65.3 C27.2 R35.1
ADC_BOW_TIMBRE
  Top 0.254: IC10.15 95.49,71.19 95.25,71.44 92.23,71.44 89.06,74.61 70.8,74.61 64.77,80.64 26.35,80.64 25.4,79.69 25.4,77.89 R11.1 C14.2 25.4,75.78 25.4,74.61 26.45,73.56 IC6.14
ADC_BRIGHTNESS
  Top 0.254: IC13.8 52.17,45.72 53.02,45.72 54.19,46.89 C42.2 R49.1 55.24,49.85 57.15,51.75 76.83,51.75 88.78,63.7 IC10.26
ADC_DAMPING
  Top 0.254: IC10.22 88.6,65.7 82.87,71.44 69.22,71.44 67.31,73.34 C20.2 | IC7.8 62.01,71.12 63.18,71.12 64.03,71.97 C20.2 | C20.2 R18.1
ADC_FM
  Top 0.254: 97.47,70.41 IC10.11 97.49,72.05 97.16,72.39 97.16,74.93 96.2,75.88 71.44,75.88 65.41,81.92 25.4,81.92 23.81,80.33 23.81,77.79 19.37,73.34 R28.1 C25.2 17.78,66.36 16.51,65.09 IC9.7
ADC_GEOMETRY
  Top 0.254: IC10.23 88.15,65.2 82.55,70.8 64.14,70.8 61.91,68.58 61.91,66.04 | IC7.7 61.91,66.04 | R29.1 C28.2 63.4,66.04 61.91,66.04
ADC_POSITION
  Top 0.254: IC10.25 88.33,64.2 76.52,52.39 43.81,52.39 42.33,50.9 R48.1 C41.2 42.23,47.84 42.23,46.67 43.28,45.62 IC13.14
ADC_POTS  (via drill 0.6)
  Top 0.254: IC8.3 128.95,66.99 v130.18,66.99 | v130.18,52.07 130.16,52.09 IC11.3 | IC5.3 128.95,73.66 v130.18,73.66 | IC3.3 128.95,84.45 v130.18,84.45 130.18,80.64 128.91,79.38 118.11,79.38 | v102.23,74.61 102.55,74.3 106.36,74.3 111.44,79.38 118.11,79.38 | v99.06,73.03 98.99,72.96 IC10.8 | 118.11,79.38 TP1.P$1
  Bottom 0.254: v130.18,84.45 130.18,82.23 130.49,81.92 130.49,73.98 v130.18,73.66 130.18,71.12 130.49,70.8 130.49,67.31 v130.18,66.99 130.18,61.28 129.22,60.33 129.22,59.05 130.49,57.78 130.49,52.39 v130.18,52.07 | v102.23,74.61 100.65,73.03 v99.06,73.03
ADC_PRESSURE
  Top 0.254: IC10.14 95.99,71.49 95.57,71.91 92.71,71.91 89.38,75.25 71.12,75.25 65.09,81.28 25.72,81.28 24.45,80.01 24.45,74.3 27.62,71.12 IC6.1 26.14,67.41 24.77,66.04 24.77,65.3 C26.2 R34.1
ADC_SPACE
  Top 0.254: R73.1 C50.2 54.61,37.57 54.61,38.1 53.24,39.47 IC13.7 | IC10.27 89.24,63.2 77.15,51.12 57.47,51.12 55.24,48.9 55.24,46.35 52.07,43.18 IC13.7 | IC13.7 52.29,39.69
ADC_STRIKE_SHAPE
  Top 0.254: 92.8,66.67 IC10.20 89.51,66.7 83.5,72.71 69.85,72.71 63.82,78.74 52.7,78.74 51.12,77.15 51.12,71.75 54.29,68.58 IC7.1 52.49,64.87 51.12,63.5 51.12,62.65 C30.2 R46.1
ADC_STRIKE_TIMBRE
  Top 0.254: IC10.21 89.06,66.2 83.19,72.07 69.53,72.07 63.5,78.11 53.02,78.11 52.17,77.25 R17.1 C19.2 52.17,71.97 53.02,71.12 54.19,71.12 IC7.14
ADC_V_OCT
  Top 0.254: IC10.10 97.99,72.19 97.63,72.55 97.63,75.41 96.52,76.52 71.75,76.52 65.72,82.55 25.08,82.55 23.18,80.64 23.18,78.11 19.05,73.98 17.14,73.98 15.56,72.39 8.89,72.39 7.62,71.12 C24.2 | R27.1 C24.2 | IC9.1 8.57,66.36 8.04,66.89 C24.2
AREF_-10  (via drill 0.6)
  Top 0.254: R56.2 R55.2 v47.31,51.44 | R70.2 49.43,35.56 v47.31,35.56 | R20.2 R21.2 v59.05,76.52 | R14.2 R15.2 v32.38,79.06 | R32.2 33.34,60.96 v32.38,60.01 30.8,60.01 29.53,61.28 | R37.2 7.62,61.59 7.94,61.28 v15.24,61.28 16.51,61.28 16.93,61.7 R38.2 | v32.38,87 v52.7,87 54.29,87 54.61,87.31 v60.33,87.31 | 29.53,61.28 R31.2 | 29.53,61.28 21.91,61.28 20.64,60.01 v20.64,59.69 | R1.2 R2.2 45.5,95.57 IC1.2 49.21,95.57 49.43,95.35 C2.1 52.6,95.35 v52.7,95.25 | R42.2 63.5,57.78 61.91,56.2 v59.05,56.2 57.78,54.93 56.2,54.93 | 56.2,54.93 v47.31,54.93 | 56.2,54.93 R41.2
  Bottom 0.254: v47.31,35.56 v47.31,51.44 v47.31,54.93 | v32.38,87 v32.38,79.06 v32.38,60.01 | v60.33,87.31 60.33,85.09 58.74,83.5 58.74,76.83 v59.05,76.52 59.05,60.96 60.01,60.01 60.01,59.37 59.05,58.42 v59.05,56.2 | v52.7,87 v52.7,95.25 | v15.24,61.28 19.05,61.28 v20.64,59.69
BOOT_FLASH  (via drill 0.6)
  Top 0.254: SW3.A SW3.A' | SW3.A 161.61,52.07 | v143.19,66.04 149.86,66.04 152.4,63.5 152.4,60.64 151.45,59.69 151.45,53.34 155.79,49 R50.2 159.81,48.9 160.97,48.9 161.7,49.62 SW3.A | v123.83,66.36 126.36,68.9 133.67,68.9 134.62,69.85 137.16,69.85 v137.48,69.53 | IC10.60 112.88,66.2 114.3,67.63 115.89,67.63 116.52,66.99 120.33,66.99 123.83,70.48 v123.83,71.12
  Bottom 0.254: v143.19,66.04 139.7,69.53 v137.48,69.53 | v123.83,71.12 v123.83,66.36
GATE
  Top 0.254: R60.1 13.27,45.62 Q2.C 29.04,45.55 36.51,53.02 76.2,53.02 87.88,64.7 IC10.24
GND  (via drill 0.6)
  other vias: 138.75,78.42 138.11,87.31 139.38,53.66 105.41,55.56 100.01,38.73 98.11,83.5 101.92,83.5 100.33,51.75 90.49,50.16 106.68,67.94 90.81,58.1 123.83,80.64 127.64,70.8 127.64,64.14 127.64,67.94 128.91,47.62 71.75,43.18 74.61,37.78 65.09,44.13 94.93,42.55 91.92,74.45 96.36,66.52 101.76,65.25 17.46,82.23 85.41,81.92 17.78,71.75 13.34,63.18 31.43,60.96 88.74,69.69 66.67,61.59 42.55,37.15 48.26,43.5 56.52,68.9 30.16,71.44 73.98,43.18 75.25,80.64 81.6,81.92 75.25,65.56 80.33,65.56 60.33,68.9 33.66,71.44 91.12,84.45 115.89,75.56 119.06,75.56 134.62,79.38 141.92,74.3 133.99,55.24 129.22,76.2 92.39,15.88 97.16,15.88 97.16,12.38 92.39,12.38 28.57,17.14 21.59,17.14 20.95,33.97 28.57,33.97 28.57,48.26 20.95,47.31 25.08,70.48 20.64,70.48 2.54,88.9 48.58,103.5 76.2,47.62 65.72,49.85 69.53,69.53 66.04,69.53 66.04,89.85 70.48,88.27 66.04,54.29 27.94,28.89 46.99,33.97 44.45,33.97 50.48,43.5 44.77,43.5 138.11,46.67 146.37,46.67 86.36,65.09 50.48,78.11 64.14,85.72 27.94,88.9 73.34,58.42 37.78,48.26 124.46,33.02 119.38,48.26 120.65,53.34 119.38,83.82 144.78,78.74 149.86,27.94 78.42,29.21 104.14,29.21 83.5,53.34 37.78,59.69 37.78,55.88 138.11,28.89 146.37,28.89 124.46,93.98 96.52,96.52 70.8,96.52 53.02,104.14 63.18,104.14 73.34,104.14 83.5,104.14 93.98,104.14 104.14,104.14 114.3,104.14 124.46,104.14 134.62,104.14 144.78,104.14 154.94,104.14 162.56,97.79 162.56,7.62 162.56,17.78 162.56,27.94 162.56,38.1 162.56,48.26 151.13,1.27 138.11,1.27 125.09,1.27 12.7,12.7 12.7,27.94 12.7,48.26 12.7,58.42 1.27,99.06 1.27,78.74 1.27,68.58 1.27,58.42 1.27,48.26 1.27,38.1 1.27,27.94 111.76,1.27 95.89,1.27 79.69,1.27 66.67,1.27 53.66,1.27 40.64,1.27 144.78,88.9 99.06,88.9 109.22,48.26 58.1,44.45 32.7,38.1 55.24,85.09 99.22,63.34 110.17,59.69 91.44,80.33 40.64,7.62 147.96,53.98
  pour Bottom: 0,106.05 0,0 164.47,0 164.47,106.05
  pour Top: 0,106.05 164.47,106.05 164.47,0 0,0
I2C_SCL  (via drill 0.6)
  Top 0.254: R52.1 103.4,48.26 102.87,48.26 102.6,47.99 IC12.24 99.91,47.94 98.74,47.94 97.47,49.21 97.47,53.02 v97.16,53.34 | v96.2,62.55 95.86,62.2 IC10.29
  Bottom 0.254: v96.2,62.55 97.16,61.59 v97.16,53.34
I2C_SDA  (via drill 0.6)
  Top 0.254: R53.1 105.09,47.62 104.81,47.34 IC12.23 99.92,47.31 98.74,47.31 96.84,49.21 96.84,51.75 v96.52,52.07 | v95.57,61.28 95.14,61.7 IC10.30
  Bottom 0.254: v96.52,52.07 96.2,52.39 96.2,53.98 96.52,54.29 96.52,60.64 95.89,61.28 v95.57,61.28
I2S_LRCK
  Top 0.254: 92.41,47.94 IC12.5 90.76,47.99 | IC10.33 94.99,56.89 93.98,55.88 91.12,55.88 89.53,54.29 89.53,49.21 90.76,47.99 | IC12.7 92.44,46.67 91.44,46.67 90.76,47.35 90.76,47.99
I2S_MCK
  Top 0.254: IC12.25 98.68,48.64 98.11,49.21 98.11,53.66 96.99,54.77 IC10.37
I2S_SCK
  Top 0.254: 92.53,49.21 IC12.3 93.74,49.29 93.98,49.53 93.98,54.93 95.49,56.44 IC10.34
I2S_SIN  (via drill 0.6)
  Top 0.254: IC12.6 92.48,47.31 93.66,47.31 v95.25,48.9 | v95.25,54.93 95.99,55.67 IC10.35
  Bottom 0.254: v95.25,48.9 v95.25,54.93
I2S_SOUT
  Top 0.254: IC12.4 93.72,48.64 94.61,49.53 94.61,52.39 96.49,54.27 IC10.36
JTCK  (via drill 0.6)
  Top 0.254: v111.44,57.78 112.08,57.15 JP1.4 | v111.44,54.29 111.44,54.61 105.35,60.7 IC10.49
  Bottom 0.254: v111.44,54.29 111.76,54.61 111.76,57.47 v111.44,57.78
JTDI
  Top 0.254: JP1.8 112.39,54.61 105.8,61.2 IC10.50
JTDO
  Top 0.254: JP1.6 112.08,55.88 105.73,62.23 105.73,63.5 105.53,63.7 IC10.55
JTMS  (via drill 0.6)
  Top 0.254: IC10.46 101.49,59.27 102.23,60.01 105.09,60.01 110.49,54.61 110.49,53.98 111.12,53.34 v112.39,53.34 | v112.71,58.42 JP1.2
  Bottom 0.254: v112.39,53.34 112.39,58.1 v112.71,58.42
LED_GATE  (via drill 0.6)
  Top 0.254: 97.47,58.59 IC10.38 97.49,66.38 98.74,67.63 98.74,68.58 v98.58,68.74 | v99.06,74.61 99.06,75.88 97.16,77.79 72.39,77.79 66.36,83.82 24.45,83.82 21.91,81.28 21.91,78.74 20.11,76.94 R10.1
  Bottom 0.254: v98.58,68.74 98.11,69.22 98.11,73.66 v99.06,74.61
LIN  (via drill 0.6)
  Top 0.254: v93.66,30.16 93.34,30.48 73.66,30.48 72.07,28.89 36.51,28.89 31.75,24.13 31.75,20.32 30.48,19.05 30.47,19.06 C56.+ | v93.66,34.92 93.66,36.2 96.2,38.73 96.2,43.18 98.41,45.39 IC12.20
  Bottom 0.254: v93.66,30.16 v93.66,34.92
LOUT
  Top 0.254: C40.+ 83.82,50.18 83.82,47.31 86.68,44.45 89.53,44.45 90.55,43.44 IC12.12
LOUT_JACK
  Top 0.254: R89.1 24.34,1.91 J8.P3
N$1  (via drill 0.6)
  Top 0.254: v27.3,3.17 34.61,3.17 35.24,2.54 44.45,2.54 45.09,1.91 J10.P3 | R16.2 33.97,79.38 33.34,80.01 29.53,80.01 v28.89,79.38
  Bottom 0.254: v27.3,3.17 26.67,3.17 23.81,6.03 23.81,74.93 26.99,78.11 27.62,78.11 v28.89,79.38
N$2
  Top 0.254: R15.1 R16.1 | R16.1 IC6.9 | R16.1 35.56,75.98 C15.1 R12.2
N$3  (via drill 0.6)
  Top 0.254: v27.3,8.26 34.92,8.26 38.73,4.45 48.26,4.45 48.9,3.81 61.28,3.81 61.91,3.17 73.66,3.17 74.3,2.54 83.5,2.54 84.14,1.91 J13.P3 | v26.99,55.56 28.89,57.47 52.07,57.47 v52.7,58.1 | v53.98,76.83 54.61,76.2 54.93,76.2 55.56,75.56 R19.2
  Bottom 0.254: v52.7,58.1 52.7,75.56 v53.98,76.83 | v26.99,55.56 25.72,54.29 25.72,9.84 v27.3,8.26
N$4  (via drill 0.6)
  Top 0.254: v26.67,1.91 J9.P3 | v27.3,79.38 27.94,78.74 28.26,78.74 28.89,78.11 R13.2
  Bottom 0.254: v26.67,1.91 23.18,5.4 23.18,75.25 v27.3,79.38
N$5
  Top 0.254: R11.2 C14.1 27.3,75.98 R13.1 | IC6.13 R13.1 | R13.1 R14.1
N$6
  Top 0.254: R39.2 19.37,60.96 19.05,60.64 17.78,60.64 16.51,59.37 16.51,50.48 J2.P3
N$7
  Top 0.254: 104.78,80.07 Q1.2 | 104.78,80.07 104.78,80.96 105.31,81.5 C12.2 | 104.78,80.07 104.71,80.01 101.28,80.01 100.49,79.22 IC10.5
N$8
  Top 0.254: C11.2 94.72,81.5 95.25,80.96 95.25,80.07 Q1.1 95.25,79.95 95.31,80.01 99.06,80.01 99.99,79.08 IC10.6
N$9
  Top 0.254: IC7.13 R19.1 | R19.1 R20.1 | R17.2 C19.1 55.46,73.34 R19.1
N$10
  Top 0.254: J1.P3 6.03,48.58 4.45,50.16 4.45,61.28 5.18,62.02 R36.2
N$11
  Top 0.254: C24.1 R27.2 R36.1 | C24.1 7.52,65.09 | IC9.2 10,65.19 C24.1 | C24.1 R37.1
N$12  (via drill 0.6)
  Top 0.254: v27.94,11.11 28.26,10.79 47.94,10.79 54.29,4.45 61.59,4.45 62.23,3.81 73.98,3.81 74.61,3.17 87,3.17 87.63,2.54 102.87,2.54 103.5,1.91 J14.P3 | v28.57,55.56 29.84,56.83 v53.34,56.83 | v55.56,76.83 56.2,77.47 60.01,77.47 60.64,76.83 R22.2
  Bottom 0.254: v28.57,55.56 26.35,53.34 26.35,12.7 v27.94,11.11 | v53.34,56.83 53.66,57.15 53.66,58.42 53.34,58.74 53.34,75.25 53.98,75.88 54.61,75.88 v55.56,76.83
N$13
  Top 0.254: C35.1 101.99,55.63 IC10.47
N$14
  Top 0.254: R22.1 R21.1 | IC7.9 R22.1 | R22.1 60.74,73.34 C20.1 R18.2
N$15
  Top 0.254: IC9.6 16.51,63.82 16.93,63.4 R38.1 C25.1 R28.2 R39.1
N$16  (via drill 0.6)
  Top 0.254: v27.3,5.71 28.57,4.45 35.24,4.45 35.88,3.81 47.94,3.81 48.58,3.17 60.96,3.17 61.59,2.54 70.17,2.54 70.8,1.91 J12.P3 | v27.3,57.15 28.26,58.1 51.44,58.1 52.7,59.37 54.29,59.37 54.61,59.69 R40.2
  Bottom 0.254: v27.3,57.15 25.08,54.93 25.08,7.94 v27.3,5.71
N$17
  Top 0.254: IC12.16 98.67,42.79 98.11,42.23 98.11,40.42 C47.1 98.21,38.52 97.78,38.09 C52.+
N$18
  Top 0.254: R86.1 22.66,13.87 C57.1 R87.2 25.72,14.61 25.4,14.92 C56.-
N$19
  Top 0.254: C31.1 91.19,61.2 IC10.31
N$20
  Top 0.254: J5.P3 7.62,18.73 19.05,18.73 20.74,20.42 R75.2
N$21
  Top 0.254: R86.2 20.74,13.97 20,13.97 18.41,15.56 J6.P3
N$22
  Top 0.254: R75.1 22.97,27.09 C54.1 R74.2 25.72,26.67 25.4,26.35 C55.-
N$23
  Top 0.254: R58.2 R59.2 74.72,49.21 77.15,49.21 78.42,50.48 C40.-
N$24
  Top 0.254: IC7.2 55.56,63.82 56.2,63.18 R41.1 R40.1 54.51,62.55 C30.1 R46.2
N$25
  Top 0.254: IC14.6 71.12,46.35 71.33,46.57 C43.1 | R58.1 72.92,47.31 C43.1 | C43.1 R51.2
N$26  (via drill 0.6)
  Top 0.254: v26.67,4.45 27.62,4.45 28.26,3.81 34.92,3.81 35.56,3.17 47.62,3.17 48.26,2.54 57.47,2.54 58.1,1.91 J11.P3 | v26.35,58.74 26.67,59.05 33.34,59.05 34.92,60.64 R33.2
  Bottom 0.254: v26.67,4.45 24.45,6.67 24.45,56.83 v26.35,58.74
N$27
  Top 0.254: IC6.6 33.97,66.36 33.34,65.72 R32.1 R33.1 35.03,65.09 C27.1 R35.2
N$28  (via drill 0.6)
  Top 0.254: v66.36,34.92 66.36,40.01 69.85,43.5 IC14.7 69.85,46.35 69.64,46.57 C43.2 R51.1 | v66.36,32.38 66.04,32.07 25.4,32.07 24.77,32.7 20.95,32.7 18.41,30.16 5.71,30.16 2.22,26.67 2.22,5.08 3.81,3.49 11.11,3.49 11.33,3.71 R88.2
  Bottom 0.254: v66.36,32.38 v66.36,34.92
N$29  (via drill 0.6)
  Top 0.254: v95.25,25.72 94.93,26.04 93.34,26.04 93.03,25.72 49.85,25.72 v49.53,26.04 | v49.53,51.44 50.8,50.16 R57.2 | v95.89,8.26 99.69,4.45 106.68,4.45 107.31,3.81 126.05,3.81 126.68,3.17 138.43,3.17 139.7,1.91 J17.P3
  Bottom 0.254: v95.25,25.72 95.25,24.13 94.93,23.81 94.93,9.21 v95.89,8.26 | v49.53,26.04 v49.53,51.44
N$30
  Top 0.254: R57.1 IC13.9 | R56.1 R57.1 | R49.2 C42.1 52.39,48.05 R57.1
N$31
  Top 0.254: R68.2 R69.2 73.13,35.88 74.61,35.88 75.23,35.26 C53.-
N$32
  Top 0.254: IC14.2 69.75,39.84 C49.1 | C49.1 R72.2 | R68.1 71.33,37.78 C49.1
N$33  (via drill 0.6)
  Top 0.254: v68.26,32.07 67.63,31.43 25.08,31.43 24.45,32.07 21.27,32.07 18.73,29.53 6.03,29.53 2.86,26.35 2.86,5.71 4.45,4.13 10.79,4.13 11.43,4.76 13.34,4.76 14.39,3.71 R89.2 | v68.26,34.61 68.05,34.82 R72.1 C49.2 67.94,37.88 67.94,39.37 68.52,39.95 IC14.1
  Bottom 0.254: v68.26,32.07 v68.26,34.61
N$34  (via drill 0.6)
  Top 0.254: v50.8,34.29 51.12,34.61 R71.2 | v49.53,24.13 49.85,24.45 93.03,24.45 93.34,24.13 v96.2,24.13 | v95.89,10.79 98.42,8.26 106.68,8.26 110.49,4.45 126.36,4.45 127,3.81 138.75,3.81 139.06,3.49 151.13,3.49 152.72,1.91 J18.P3
  Bottom 0.254: v49.53,24.13 50.8,25.4 v50.8,34.29 | v96.2,24.13 95.57,23.5 95.57,11.11 v95.89,10.79
N$35
  Top 0.254: R70.1 R71.1 | R71.1 51.22,37.47 C50.1 R73.2 | R71.1 51.12,38.1 50.8,38.42 IC13.6
N$36  (via drill 0.6)
  Top 0.254: v28.26,53.02 28.89,53.66 60.64,53.66 65.09,58.1 R43.2 | v28.26,13.65 47.94,13.65 53.34,8.26 61.91,8.26 65.72,4.45 74.3,4.45 74.93,3.81 87.31,3.81 87.95,3.17 106.05,3.17 106.68,2.54 115.57,2.54 116.2,1.91 J15.P3
  Bottom 0.254: v28.26,53.02 26.99,51.75 26.99,14.92 v28.26,13.65
N$37
  Top 0.254: 60.64,64.14 IC7.6 60.64,63.5 60.96,63.18 63.5,63.18 | R29.2 C28.1 63.5,63.18 | 63.5,63.18 R42.1 R43.1
N$38
  Top 0.254: R10.2 17.44,78.66 SW1.L1
N$39  (via drill 0.6)
  Top 0.254: v45.72,51.44 R54.2 | v45.72,25.08 v93.98,25.08 | v94.3,4.45 94.93,3.81 106.36,3.81 107,3.17 125.73,3.17 127,1.91 J16.P3
  Bottom 0.254: v93.98,25.08 94.3,24.77 v94.3,4.45 | v45.72,25.08 v45.72,51.44
N$40
  Top 0.254: IC13.13 R54.1 | R54.1 R55.1 | R54.1 45.62,47.94 C41.1 R48.2
N$41  (via drill 0.6)
  Top 0.254: R30.2 27.94,62.55 27.3,61.91 21.59,61.91 19.68,60.01 19.68,57.15 20,56.83 20,55.24 20.64,54.61 20.64,48.58 19.37,47.31 v16.19,47.31
  Bottom 0.254: v16.19,47.31 16.19,35.24 J4.P3
N$42
  Top 0.254: R34.2 C26.1 27.84,65.09 R30.1 R31.1 29.53,65.72 28.89,66.36 IC6.2
N$43
  Top 0.254: J3.P3 9.53,33.02 12.38,35.88 R67.1
N$44
  Top 0.254: IC13.1 IC13.2
N$45
  Top 0.254: IC11.14 136.19,52.09 139.38,48.9 139.38,27.3 137.48,25.4 108.27,25.4 102.55,19.68 37.15,19.68 33.97,16.51 R76.P$2
N$46
  Top 0.254: R65.P$2 131.44,40.32 136.53,45.4 136.53,50.8 135.89,51.44 IC11.13
N$47  (via drill 0.6)
  Top 0.254: IC11.15 136.5,52.73 140.02,49.21 140.02,26.99 137.79,24.77 108.58,24.77 102.87,19.05 47.62,19.05 v46.99,18.41
  Bottom 0.254: R77.P$2 v46.99,18.41
N$48
  Top 0.254: R64.P$2 107.63,36.2 108.27,36.83 115.89,36.83 124.78,45.72 124.78,51.12 127.05,53.38 IC11.1
N$49
  Top 0.254: R61.P$2 36.2,33.66 37.15,32.7 65.09,32.7 65.72,33.34 66.99,33.34 67.31,33.02 69.22,33.02 69.53,32.7 72.39,32.7 73.34,31.75 113.67,31.75 126.68,44.77 126.68,50.16 127.3,50.78 IC11.5
N$50
  Top 0.254: R80.P$2 86.04,16.51 86.68,17.14 103.82,17.14 105.73,19.05 140.97,19.05 142.88,20.95 142.88,24.13 141.92,25.08 141.92,57.15 139.06,60.01 139.06,61.91 137.79,63.18 137.79,65.09 135.88,67.01 IC8.14
N$51
  Top 0.254: R78.P$2 60.01,16.51 61.91,18.41 103.19,18.41 108.9,24.13 138.11,24.13 140.65,26.67 140.65,56.52 137.79,59.37 137.79,61.28 136.53,62.55 136.53,64.45 135.27,65.71 IC8.12
N$52
  Top 0.254: R63.P$2 83.82,33.66 84.45,33.02 113.03,33.02 125.41,45.4 125.41,50.8 127.35,52.73 IC11.2
N$53
  Top 0.254: R62.P$2 60.01,33.66 60.33,33.34 64.77,33.34 65.41,33.97 67.31,33.97 67.63,33.66 69.53,33.66 69.85,33.34 72.71,33.34 73.66,32.38 113.35,32.38 126.05,45.09 126.05,50.48 127,51.44 IC11.4
N$54  (via drill 0.6)
  Top 0.254: v102.87,62.23 100.49,59.85 IC10.44 | v107.31,62.23 108.58,63.5 120.33,63.5 122.24,61.59 122.24,60.96 v121.92,60.64 | v124.14,62.87 124.56,62.45 R44.1
  Bottom 0.254: v102.87,62.23 v107.31,62.23 | v121.92,60.64 v124.14,62.87
N$55
  Top 0.254: IC3.12 136.54,83.17 139.7,80.01 139.7,72.71 140.97,71.44 140.97,67.63 141.6,66.99 141.6,65.09 142.88,63.82 142.88,61.91 145.73,59.05 145.73,49.53 155.26,40.01 R66.P$2
N$56
  Top 0.406: JP3.2 JP3.1 19.05,103.19 D1.A
N$57
  Top 0.254: R81.P$2 105.41,16.83 107,18.41 141.29,18.41 143.51,20.64 143.51,24.45 142.56,25.4 142.56,57.47 139.7,60.33 139.7,62.23 138.43,63.5 138.43,65.41 136.18,67.66 IC8.15
N$58
  Top 0.254: R79.P$2 73.03,16.51 74.3,17.78 103.5,17.78 105.41,19.68 140.65,19.68 142.24,21.27 142.24,23.81 141.29,24.77 141.29,56.83 138.43,59.69 138.43,61.59 137.16,62.87 137.16,64.77 135.57,66.36 IC8.13
N$59
  Top 0.254: R44.2 127.1,60.64 129.22,60.64 LED2.A
N$60
  Top 0.254: R47.2 61.28,57.89 LED1.A
N$61  (via drill 0.6)
  Top 0.406: IC4.3 72.64,81.28 71.44,81.28 68.26,84.45 v68.26,86.68 | v68.26,94.61 67.63,93.98 27.41,93.98 C5.1 27.2,93.98 L1.2
  Bottom 0.406: v68.26,94.61 v68.26,86.68
N$62
  Top 0.254: R26.P$2 147.96,63.5 146.69,64.77 142.88,64.77 142.24,65.41 142.24,67.31 141.6,67.94 141.6,71.75 140.34,73.03 140.34,80.33 136.84,83.82 IC3.13
N$63
  Top 0.254: R8.P$2 131.44,86.36 132.69,85.12 IC3.15
N$64
  Top 0.406: JP3.10 JP3.9 30.48,103.19 D2.C
N$65
  Top 0.254: R82.P$2 118.43,16.51 119.7,17.78 141.6,17.78 144.15,20.32 144.15,24.77 143.19,25.72 143.19,57.78 140.34,60.64 140.34,62.55 139.06,63.82 139.06,65.72 138.43,66.36 138.43,70.17 136.22,72.38 IC5.12
N$66
  Top 0.254: R67.2 Q2.B
N$67  (via drill 0.6)
  Top 0.254: v123.51,83.82 123.51,84.14 117.47,90.17 114.3,90.17 111.76,87.63 107.95,87.63 107.63,87.95 R7.P$2 | v124.46,73.03 IC5.4
  Bottom 0.254: v123.51,83.82 123.51,82.55 125.09,80.96 125.09,76.52 124.46,75.88 v124.46,73.03
N$68
  Top 0.254: IC3.14 134.6,84.45 152.4,84.45 155.26,87.31 R9.P$2
N$69  (via drill 0.6)
  Top 0.254: R6.P$2 83.82,90.49 84.14,90.81 117.79,90.81 124.78,83.82 v124.78,82.87 | v125.41,74.3 127.95,74.3 127.98,74.33 IC5.2
  Bottom 0.254: v124.78,82.87 125.73,81.92 125.73,76.2 125.41,75.88 v125.41,74.3
N$70  (via drill 0.6)
  Top 0.254: 128.92,72.39 IC5.5 126.67,72.38 120.65,66.36 115.25,66.36 v114.94,66.67
  Bottom 0.254: R24.P$2 v114.94,66.67
N$71  (via drill 0.6)
  Top 0.254: v76.52,88.9 76.52,90.49 77.47,91.44 118.11,91.44 126.36,83.19 v126.36,82.55 | v126.36,75.25 126.64,74.97 IC5.1
  Bottom 0.254: R23.P$2 v76.52,88.9 | v126.36,82.55 v126.36,75.25
N$72  (via drill 0.6)
  Top 0.254: v43.5,89.22 43.5,90.49 44.13,91.12 59.69,91.12 60.33,91.76 75.88,91.76 76.83,92.71 118.75,92.71 127.64,83.82 IC3.4 | R25.P$2 v43.5,77.47
  Bottom 0.254: v43.5,77.47 v43.5,89.22
N$73
  Top 0.254: R4.P$2 36.2,90.49 36.83,91.12 43.18,91.12 43.81,91.76 59.37,91.76 60.01,92.39 75.56,92.39 76.52,93.34 119.06,93.34 127.29,85.12 IC3.2
N$74
  Top 0.254: R3.P$2 12.38,90.49 13.02,91.12 35.88,91.12 36.51,91.76 42.86,91.76 43.5,92.39 59.05,92.39 59.69,93.03 75.25,93.03 76.2,93.98 119.38,93.98 127.59,85.77 IC3.1
N$75
  Top 0.254: R5.P$2 60.01,90.49 60.64,91.12 76.2,91.12 77.15,92.08 118.43,92.08 127.33,83.17 IC3.5
N$76
  Top 0.254: R83.P$2 131.44,16.51 132.08,17.14 141.92,17.14 144.78,20 144.78,25.08 143.83,26.04 143.83,58.1 140.97,60.96 140.97,62.87 139.7,64.14 139.7,66.04 139.06,66.67 139.06,70.48 136.53,73.03 IC5.13
N$77
  Top 0.254: R84.P$2 144.46,18.73 145.41,19.68 145.41,25.4 144.46,26.35 144.46,58.42 141.6,61.28 141.6,63.18 140.34,64.45 140.34,66.36 139.7,66.99 139.7,70.8 136.83,73.67 IC5.14
N$78
  Top 0.254: R85.P$2 157.48,19.05 155.57,20.95 155.57,26.67 145.1,37.15 145.1,58.74 142.24,61.59 142.24,63.5 140.97,64.77 140.97,66.67 140.34,67.31 140.34,71.12 137.13,74.33 IC5.15
N$79  (via drill 0.6)
  Top 0.254: v99.06,77.15 98.74,77.15 97.47,78.42 72.71,78.42 66.67,84.45 57.78,84.45 v57.47,84.77 | v98.42,65.72 98.11,65.41 98.11,60.64 98.99,59.76 IC10.41 | v57.47,57.47 57.78,57.78 R47.1
  Bottom 0.254: v99.06,77.15 99.06,76.2 98.11,75.25 98.11,74.61 97.47,73.98 97.47,68.26 98.42,67.31 v98.42,65.72 | v57.47,57.47 57.47,60.64 57.15,60.96 57.15,63.5 57.47,63.82 v57.47,84.77
N$80
  Top 0.406: L2.2 7.37,88.1 C4.1 7.52,86.78 7.94,86.36 9.27,86.36 IC2.3
RESET  (via drill 0.6)
  Top 0.254: R45.1 159.7,63.18 159.29,63.59 SW2.B | SW2.B SW2.B' | 115.57,51.44 121.92,51.44 125.73,55.24 129.22,55.24 131.44,57.47 137.16,57.47 137.48,57.15 v138.75,57.15 | SW2.B 156.94,63.59 156.21,62.87 156.21,58.74 155.57,58.1 v153.35,58.1 | v100.97,57.15 100.65,56.83 100.65,54.93 101.28,54.29 108.27,54.29 111.12,51.44 115.57,51.44 | v100.33,66.99 99.49,67.83 IC10.7 | 115.57,51.44 JP1.10
  Bottom 0.254: v138.75,57.15 139.06,56.83 152.4,56.83 153.35,57.78 v153.35,58.1 | v100.33,66.99 100.33,60.64 100.97,60.01 v100.97,57.15
RIN  (via drill 0.6)
  Top 0.254: 98.74,44.77 99.92,44.77 IC12.19 98.71,44.74 96.84,42.86 96.84,38.42 95.25,36.83 v95.25,34.29 | v95.25,30.8 94.93,31.11 73.34,31.11 71.75,29.53 30.16,29.53 26.99,26.35 26.99,22.23 26.66,21.89 C55.+
  Bottom 0.254: v95.25,30.8 v95.25,34.29
ROUT
  Top 0.254: IC12.13 91.36,42.79 90.81,42.23 90.81,40.01 89.22,38.42 80.33,38.42 78.44,36.52 C53.+
ROUT_JACK
  Top 0.254: R88.1 12.28,1.91 J7.P3
RX  (via drill 0.6)
  Top 0.254: 100.01,58.55 IC10.43 99.99,54.63 100.97,53.66 107.95,53.66 110.81,50.8 122.24,50.8 126.05,54.61 129.54,54.61 131.76,56.83 136.84,56.83 137.48,56.2 v137.79,56.2 | v154.31,60.64 154.62,60.96 154.62,73.66 160.66,79.69 JP2.4
  Bottom 0.254: v137.79,56.2 152.72,56.2 154.31,57.78 v154.31,60.64
SW_GATE
  Top 0.254: IC10.9 98.49,72.32 98.11,72.71 98.11,75.88 96.84,77.15 72.07,77.15 66.04,83.19 24.77,83.19 22.54,80.96 22.54,78.42 18.73,74.61 15.88,74.61 14.92,73.66 SW1.P5 SW1.P2
TX  (via drill 0.6)
  Top 0.254: IC10.42 99.49,54.18 100.65,53.02 107.63,53.02 110.49,50.16 122.56,50.16 126.36,53.98 129.86,53.98 132.08,56.2 136.53,56.2 137.48,55.24 v139.06,55.24 | v155.26,59.37 155.26,72.39 160.02,77.15 JP2.5
  Bottom 0.254: v139.06,55.24 140.97,55.24 141.29,55.56 153.03,55.56 155.26,57.78 v155.26,59.37
VCC  (via drill 0.6)
  Top 0.254: IC14.8 68.42,45.3 C44.1 66.89,45.4 v65.72,45.4 | v70.17,31.75 69.22,30.8 v21.59,30.8
  Top 0.406: D1.C 7.3,103.19 3.81,99.69 C3.+ 5.25,95.08 6.35,93.98 | L1.1 v20.95,93.98 6.35,93.98 | L2.1 5.71,89.59 5.71,91.44 6.35,92.08 6.35,93.98
  Bottom 0.254: v65.72,45.4 66.67,44.45 66.67,40.32 70.17,36.83 v70.17,31.75 | v21.59,30.8 21.91,31.11 21.91,91.76 20.95,92.71 v20.95,93.98
VEE  (via drill 0.6)
  Top 0.254: v75.25,40.01 74.93,39.69 74.08,39.69 C45.2 72.55,39.79 IC14.4 | v72.07,31.43 70.8,30.16 22.54,30.16 v21.91,29.53 | v23.5,96.2 25.4,98.11 30.8,98.11 33.66,100.97 C1.- | C1.- 44.23,100.89 | R2.1 R1.1 43.81,98.11 44.3,98.6 C1.-
  Top 0.406: D2.A 42.86,103.19 44.3,101.75 C1.-
  Bottom 0.254: v72.07,31.43 72.07,36.83 v75.25,40.01 | v21.91,29.53 22.54,30.16 22.54,95.25 v23.5,96.2

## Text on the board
tPlace: TP1 ADC_SCAN
tNames: RESET | SYSBOOT | Elements | cc-by-sa Olivier Gillet, 2014. v0.2
bNames: Red | Stripe | Elements | cc-by-sa Olivier Gillet, 2014. v0.2 | +12V | GND | GND | GND | -12V | Serial | GND | <TX | JTAG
